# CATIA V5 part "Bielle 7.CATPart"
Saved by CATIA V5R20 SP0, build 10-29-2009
Part number: Bielle 7
Bounding box of the stored display mesh (mm): x 50 to 90, y -113.94 to 136.337, z -165.938 to -133.542
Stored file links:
  D:\Dropbox\IAO_2011\MMS_GR1\0\video\IAO_2011_1503_rjugie\rjugie\IAO_2011_1503_rjugie\Bielle 7.CATPart
  D:\Dropbox\IAO_2011\MMS_GR1\0\video\IAO_2011_1503_rjugie\rjugie\IAO_2011_1503_rjugie\rjugie.CATProduct
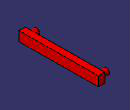
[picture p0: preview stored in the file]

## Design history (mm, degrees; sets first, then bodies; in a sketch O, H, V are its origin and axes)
External parameters (linked from other documents)
  External.Hauteur_bielle = 15 mm
  External.Epaisseur_bielle = 20 mm
  External.Rayon_trou_bielle = 10 mm
Set1
  Plane1: linked copy from another document
  Point1 "C": linked copy from another document
  Point2 "D": linked copy from another document
  Line1 "Droite.7": linked copy from another document
Body1 (main body)
  Sketch1 on Plane1, origin (0, 0, 0), H (0, 1, 0), V (0, 0, 1)
    line L1 (136.3365, -163.5405) -> (-113.652, -165.9379)
    line L2 (-113.652, -165.9379) -> (-113.9397, -135.9393)
    line L3 (-113.9397, -135.9393) -> (136.0488, -133.5419)
    line L4 (136.0488, -133.5419) -> (136.3365, -163.5405)
    reference projected point E1 (121.1934, -148.6851) from Point1
    reference projected point E2 (121.1934, -148.6851) from Point1
    reference projected point E3 (-98.7965, -150.7947) from Point2
    reference projected line E4 (-98.6811, -150.7936) -> (151.3074, -148.3963) from Line1
    reference projected line E5 (-98.6811, -150.7936) -> (151.3074, -148.3963) from Line1
    reference projected line E6 (-98.6811, -150.7936) -> (151.3074, -148.3963) from Line1
    reference projected line E7 (-98.6811, -150.7936) -> (151.3074, -148.3963) from Line1
    reference projected line E8 (-98.6811, -150.7936) -> (151.3074, -148.3963) from Line1
    distance L1 E1 = 15 {= External.Hauteur_bielle}
    distance E2 L4 = 15 {= External.Hauteur_bielle}
    distance L2 E3 = 15 {= External.Hauteur_bielle}
    distance L3 E8 = 15 {= External.Hauteur_bielle}
    parallelism: L3 E4, L1 E5
    perpendicularity: L2 E6, L4 E7
  Pad1: profile Sketch1, direction (1, 0, 0), length 70 {= 50mm+External.Epaisseur_bielle}, opposite side length -90 {= -50mm-2*External.Epaisseur_bielle}
  Sketch2 on Plane1, origin (0, 0, 0), H (0, 1, 0), V (0, 0, 1)
    circle A1 centre (-98.7965, -150.7947) radius 10
    point P1 (-98.7965, -150.7947)
    reference projected point E1 (-98.7965, -150.7947) from Point2
    circle A2 centre (121.1934, -148.6851) radius 10
    point P2 (121.1934, -148.6851)
    reference projected point E2 (121.1934, -148.6851) from Point1
    radius A1 = 10 {= External.Rayon_trou_bielle}
    radius A2 = 10 {= External.Rayon_trou_bielle}
    coincidence: P1 E1, P2 E2
  Pad2: profile Sketch2, direction (1, 0, 0), length 70 {= 50mm+External.Epaisseur_bielle}, opposite side length -50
